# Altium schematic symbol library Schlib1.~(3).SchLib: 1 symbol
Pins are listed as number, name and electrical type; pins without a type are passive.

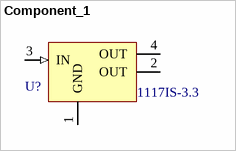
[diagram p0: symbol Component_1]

## Component_1
designator U?, comment 1117IS-3.3
footprint SOT223_N (Footprint not found)
pins: 1 GND, 2 OUT, 3 IN (in), 4 OUT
